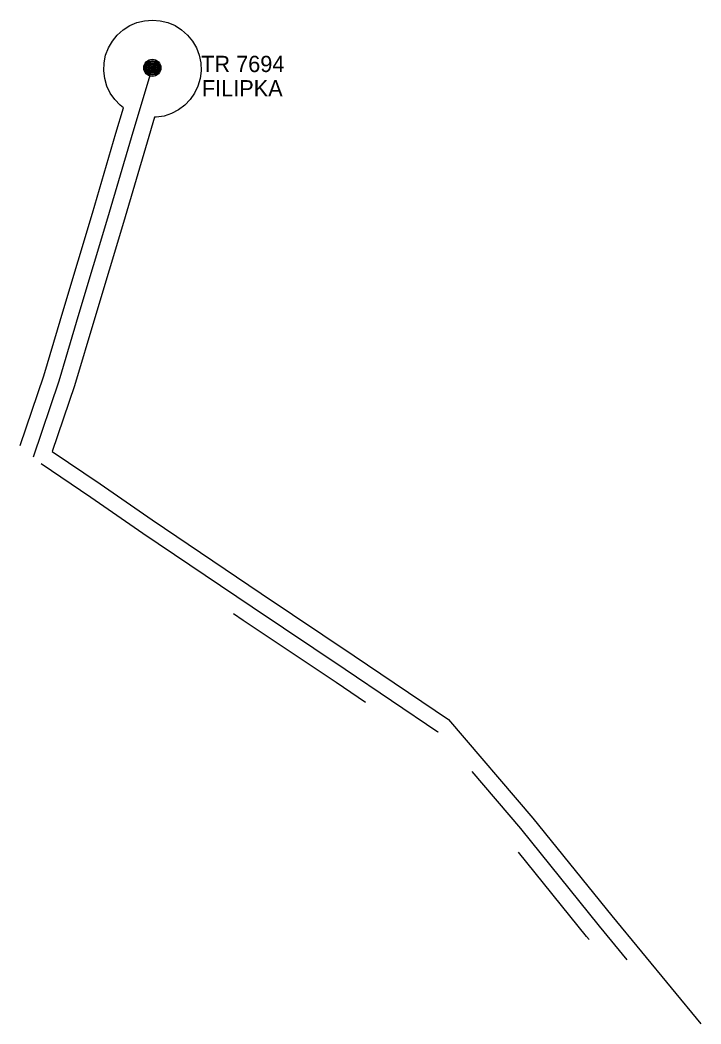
# Model space of a CAD drawing. Extents: x -439095 to -431527, y -1129525 to -1119219.
# Drawn here: x -436127 to -435708, y -1129525 to -1128907 of the extents above; entities that cross this region are included whole.
import ezdxf

# ---------------------------------------------------------------- set-up
doc = ezdxf.new("R2010")
doc.units = 0
for name, color, linetype in [('Hranice reseneho uzemi', 7, 'Continuous'), ('Vrstva 11', 7, 'Continuous'), ('Vrstva 13', 7, 'Continuous'), ('ZU', 7, 'Continuous')]:
    doc.layers.add(name, color=color, linetype=linetype)

msp = doc.modelspace()

# ---------------------------------------------------------------- linework, layer by layer
at = {"layer": 'Hranice reseneho uzemi'}
for points in [[(-436118.97, -1129175.73), (-436103.05, -1129129.02), (-436090.64, -1129087.28), (-436072.97, -1129028.48), (-436058.42, -1128979.12), (-436058.42, -1128979.12), (-436045.78, -1128936.61), (-436045.65, -1128936.11)], [(-436114.14, -1129179.87), (-436083.54, -1129200.57), (-436083.54, -1129200.57), (-436051.43, -1129222.83), (-435984.18, -1129268.23), (-435926.85, -1129306.63), (-435869.79, -1129345.24), (-435869.65, -1129345.4)], [(-435848.84, -1129369.7), (-435818.82, -1129404.77), (-435770.25, -1129464.95), (-435753.15, -1129485.66)]]:
    msp.add_lwpolyline(points, dxfattribs=at)
at = {"layer": 'Vrstva 11'}
for radius in [5.25, 4.55, 3.85, 3.15, 2.45, 1.75, 1.05, 0.35]:
    msp.add_circle((-436045.64, -1128936.14), radius, dxfattribs=at)
at = {"layer": 'ZU'}
for points in [[(-436063.39, -1128960.75), (-436065.49, -1128959.18), (-436068.83, -1128955.7), (-436071.58, -1128951.72), (-436073.64, -1128947.36), (-436074.99, -1128942.72), (-436075.57, -1128937.93), (-436075.38, -1128933.11), (-436074.41, -1128928.38), (-436072.7, -1128923.86), (-436070.28, -1128919.68), (-436067.23, -1128915.94), (-436063.62, -1128912.74), (-436059.54, -1128910.16), (-436055.09, -1128908.27), (-436050.41, -1128907.11), (-436045.59, -1128906.72), (-436040.78, -1128907.11), (-436036.09, -1128908.27), (-436031.65, -1128910.16), (-436027.57, -1128912.74), (-436023.96, -1128915.94), (-436020.9, -1128919.68), (-436018.49, -1128923.86), (-436016.78, -1128928.38), (-436015.81, -1128933.11), (-436015.62, -1128937.93), (-436016.2, -1128942.72), (-436017.54, -1128947.36), (-436019.61, -1128951.72), (-436022.36, -1128955.7), (-436025.7, -1128959.18), (-436029.56, -1128962.08), (-436033.84, -1128964.32), (-436038.41, -1128965.85), (-436043.18, -1128966.63), (-436044.27, -1128966.63)], [(-436127.15, -1129168.73), (-436112.58, -1129125.98), (-436100.22, -1129084.42), (-436082.55, -1129025.63), (-436068.07, -1128976.49), (-436068.07, -1128976.48), (-436063.39, -1128960.75)], [(-436044.27, -1128966.63), (-436048.8, -1128981.85), (-436063.38, -1129031.33), (-436081.06, -1129090.14), (-436093.52, -1129132.06), (-436107.28, -1129172.44), (-436077.87, -1129192.33), (-436077.82, -1129192.37), (-436045.78, -1129214.57), (-435978.6, -1129259.93), (-435921.27, -1129298.33), (-435863.07, -1129337.71), (-435862.05, -1129338.9)], [(-435914.32, -1129327.18), (-435932.44, -1129314.92), (-435989.76, -1129276.53), (-435995.57, -1129272.6)], [(-435863.07, -1129337.71), (-435811.12, -1129398.37), (-435762.5, -1129458.63), (-435707.57, -1129525.16)], [(-435776.43, -1129473.17), (-435778, -1129471.27), (-435819.93, -1129419.31)]]:
    msp.add_lwpolyline(points, dxfattribs=at)

# ---------------------------------------------------------------- texts
at = {"layer": 'Vrstva 13'}
for s, p in [('TR 7694', (-436015.54, -1128938.74)), ('FILIPKA', (-436015.12, -1128953.74))]:
    msp.add_text(s, height=10, dxfattribs=at).set_placement(p)

doc.saveas('drawing.dxf')
